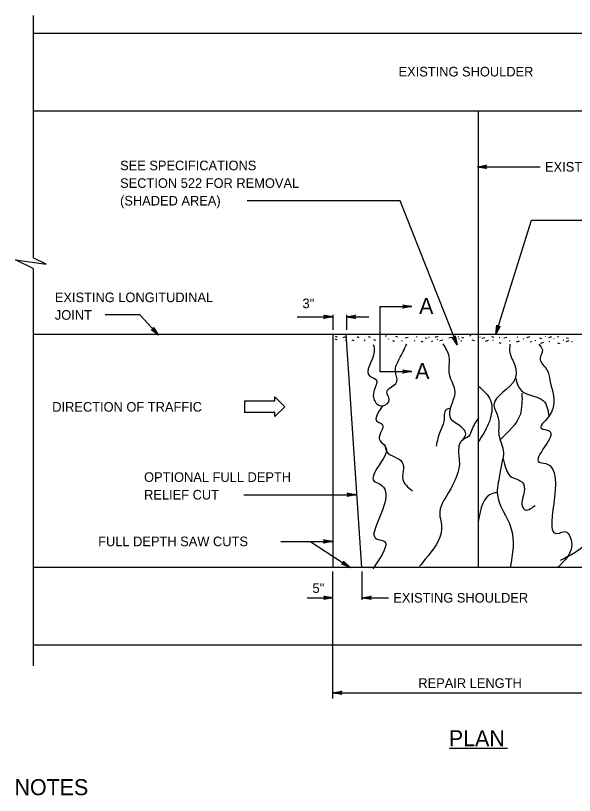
# Model space of a CAD drawing. Extents: x 1.45 to 8.06, y 0.17 to 9.98.
# Drawn here: x 1.461 to 4.954, y 5.108 to 9.976 of the extents above; entities that cross this region are included whole.
import ezdxf

# ---------------------------------------------------------------- set-up
doc = ezdxf.new("R2010")
doc.units = 0
for name, color, linetype in [('DETL-DIMS', 7, 'Continuous'), ('DETL-LINE', 7, 'Continuous'), ('DETL-NOTE', 7, 'Continuous'), ('DETL-PATT', 7, 'Continuous'), ('DETL-TITL', 7, 'Continuous')]:
    doc.layers.add(name, color=color, linetype=linetype)

msp = doc.modelspace()

# ---------------------------------------------------------------- linework, layer by layer
at = {"layer": 'DETL-DIMS'}
for p, q in [((4.3469, 9.0319), (4.7396, 9.0319)), ((4.3469, 9.0319), (4.7396, 9.0319)), ((3.8636, 8.8204), (2.9091, 8.8204)), ((3.8636, 8.8204), (2.9091, 8.8204)), ((4.2201, 7.9197), (3.8636, 8.8204)), ((4.2201, 7.9197), (3.8636, 8.8204)), ((4.462, 7.987), (4.6853, 8.6995)), ((4.6853, 8.6995), (5.057, 8.6995)), ((4.6853, 8.6995), (4.8907, 8.6995)), ((3.7368, 8.1593), (3.938, 8.1593)), ((3.7368, 8.1593), (3.7368, 7.7526)), ((3.7368, 8.1593), (3.938, 8.1593)), ((3.7368, 8.1593), (3.7368, 7.7526)), ((2.2385, 8.1071), (2.021, 8.1071)), ((2.2385, 8.1071), (2.021, 8.1071)), ((2.3533, 7.9802), (2.2385, 8.1071)), ((2.3533, 7.9802), (2.2385, 8.1071)), ((3.2205, 8.0952), (3.4438, 8.0952)), ((3.2205, 8.0952), (3.4438, 8.0952)), ((3.4438, 8.1081), (3.4438, 8.015)), ((3.4438, 8.1081), (3.4438, 8.015)), ((3.53, 8.1081), (3.53, 8.015)), ((3.53, 8.1081), (3.53, 8.015)), ((3.53, 8.0952), (3.6695, 8.0952)), ((3.53, 8.0952), (3.6695, 8.0952)), ((3.7368, 7.7537), (3.938, 7.7537)), ((3.7368, 7.7537), (3.938, 7.7537)), ((2.8924, 7.5708), (2.8924, 7.4958)), ((2.8924, 7.5708), (2.8924, 7.4958)), ((2.8884, 6.9849), (3.5893, 6.9849)), ((2.8884, 6.9849), (3.5893, 6.9849)), ((3.1188, 6.6935), (3.4429, 6.6935)), ((3.1188, 6.6935), (3.4429, 6.6935)), ((3.3063, 6.6902), (3.5531, 6.5305)), ((3.3063, 6.6902), (3.5531, 6.5305)), ((3.4438, 5.7125), (3.4438, 6.5066)), ((3.4438, 5.7158), (3.4438, 6.5066)), ((3.6264, 6.3295), (3.6264, 6.5066)), ((3.6264, 6.3295), (3.6264, 6.5066)), ((3.2823, 6.3416), (3.4438, 6.3416)), ((3.2823, 6.3416), (3.4438, 6.3416)), ((3.6264, 6.3416), (3.7916, 6.3416)), ((3.6264, 6.3416), (3.7916, 6.3416)), ((3.4438, 5.7487), (5.2619, 5.7487)), ((3.4438, 5.7487), (5.2619, 5.7487))]:
    msp.add_line(p, q, dxfattribs=at)
for points in [[(4.3469, 9.0319), (4.4034, 9.0425), (4.3991, 9.0395), (4.3968, 9.0357), (4.3962, 9.0319), (4.3968, 9.0281), (4.3991, 9.0244), (4.4034, 9.0213), (4.3469, 9.0319), (4.3991, 9.0244), (4.3968, 9.0281), (4.3469, 9.0319), (4.3962, 9.0319), (4.3968, 9.0357), (4.3469, 9.0319), (4.3991, 9.0395)], [(4.3469, 9.0319), (4.4034, 9.0425), (4.3991, 9.0395), (4.3968, 9.0357), (4.3962, 9.0319), (4.3968, 9.0281), (4.3991, 9.0244), (4.4034, 9.0213), (4.3469, 9.0319), (4.3991, 9.0244), (4.3968, 9.0281), (4.3469, 9.0319), (4.3962, 9.0319), (4.3968, 9.0357), (4.3469, 9.0319), (4.3991, 9.0395)], [(3.938, 8.1593), (3.8816, 8.1487), (3.8859, 8.1518), (3.8882, 8.1555), (3.8888, 8.1593), (3.8882, 8.1631), (3.8859, 8.1669), (3.8816, 8.1699), (3.938, 8.1593), (3.8859, 8.1669), (3.8882, 8.1631), (3.938, 8.1593), (3.8888, 8.1593), (3.8882, 8.1555), (3.938, 8.1593), (3.8859, 8.1518)], [(3.938, 8.1593), (3.8816, 8.1487), (3.8859, 8.1518), (3.8882, 8.1555), (3.8888, 8.1593), (3.8882, 8.1631), (3.8859, 8.1669), (3.8816, 8.1699), (3.938, 8.1593), (3.8859, 8.1669), (3.8882, 8.1631), (3.938, 8.1593), (3.8888, 8.1593), (3.8882, 8.1555), (3.938, 8.1593), (3.8859, 8.1518)], [(3.938, 8.1593), (3.8816, 8.1487), (3.8859, 8.1518), (3.8882, 8.1555), (3.8888, 8.1593), (3.8882, 8.1631), (3.8859, 8.1669), (3.8816, 8.1699), (3.938, 8.1593), (3.8859, 8.1669), (3.8882, 8.1631), (3.938, 8.1593), (3.8888, 8.1593), (3.8882, 8.1555), (3.938, 8.1593), (3.8859, 8.1518)], [(3.938, 8.1593), (3.8816, 8.1487), (3.8859, 8.1518), (3.8882, 8.1555), (3.8888, 8.1593), (3.8882, 8.1631), (3.8859, 8.1669), (3.8816, 8.1699), (3.938, 8.1593), (3.8859, 8.1669), (3.8882, 8.1631), (3.938, 8.1593), (3.8888, 8.1593), (3.8882, 8.1555), (3.938, 8.1593), (3.8859, 8.1518)], [(3.4438, 8.0952), (3.3873, 8.0846), (3.3916, 8.0877), (3.3939, 8.0915), (3.3945, 8.0952), (3.3939, 8.099), (3.3916, 8.1028), (3.3873, 8.1058), (3.4438, 8.0952), (3.3916, 8.1028), (3.3939, 8.099), (3.4438, 8.0952), (3.3945, 8.0952), (3.3939, 8.0915), (3.4438, 8.0952), (3.3916, 8.0877)], [(3.4438, 8.0952), (3.3873, 8.0846), (3.3916, 8.0877), (3.3939, 8.0915), (3.3945, 8.0952), (3.3939, 8.099), (3.3916, 8.1028), (3.3873, 8.1058), (3.4438, 8.0952), (3.3916, 8.1028), (3.3939, 8.099), (3.4438, 8.0952), (3.3945, 8.0952), (3.3939, 8.0915), (3.4438, 8.0952), (3.3916, 8.0877)], [(3.53, 8.0952), (3.5864, 8.1058), (3.5821, 8.1028), (3.5798, 8.099), (3.5792, 8.0952), (3.5798, 8.0915), (3.5821, 8.0877), (3.5864, 8.0846), (3.53, 8.0952), (3.5821, 8.0877), (3.5798, 8.0915), (3.53, 8.0952), (3.5792, 8.0952), (3.5798, 8.099), (3.53, 8.0952), (3.5821, 8.1028)], [(3.53, 8.0952), (3.5864, 8.1058), (3.5821, 8.1028), (3.5798, 8.099), (3.5792, 8.0952), (3.5798, 8.0915), (3.5821, 8.0877), (3.5864, 8.0846), (3.53, 8.0952), (3.5821, 8.0877), (3.5798, 8.0915), (3.53, 8.0952), (3.5792, 8.0952), (3.5798, 8.099), (3.53, 8.0952), (3.5821, 8.1028)], [(4.462, 7.987), (4.4688, 8.0441), (4.4704, 8.0391), (4.4733, 8.0358), (4.4767, 8.034), (4.4805, 8.0335), (4.4848, 8.0345), (4.489, 8.0378), (4.462, 7.987), (4.4848, 8.0345), (4.4805, 8.0335), (4.462, 7.987), (4.4767, 8.034), (4.4733, 8.0358), (4.462, 7.987), (4.4704, 8.0391)], [(2.3533, 7.9802), (2.3076, 8.015), (2.3127, 8.0137), (2.317, 8.0146), (2.3203, 8.0167), (2.3227, 8.0197), (2.324, 8.0239), (2.3233, 8.0292), (2.3533, 7.9802), (2.324, 8.0239), (2.3227, 8.0197), (2.3533, 7.9802), (2.3203, 8.0167), (2.317, 8.0146), (2.3533, 7.9802), (2.3127, 8.0137)], [(2.3533, 7.9802), (2.3076, 8.015), (2.3127, 8.0137), (2.317, 8.0146), (2.3203, 8.0167), (2.3227, 8.0197), (2.324, 8.0239), (2.3233, 8.0292), (2.3533, 7.9802), (2.324, 8.0239), (2.3227, 8.0197), (2.3533, 7.9802), (2.3203, 8.0167), (2.317, 8.0146), (2.3533, 7.9802), (2.3127, 8.0137)], [(4.2201, 7.9197), (4.1894, 7.9683), (4.1939, 7.9654), (4.1982, 7.9647), (4.202, 7.9655), (4.2052, 7.9675), (4.2079, 7.971), (4.2091, 7.9761), (4.2201, 7.9197), (4.2079, 7.971), (4.2052, 7.9675), (4.2201, 7.9197), (4.202, 7.9655), (4.1982, 7.9647), (4.2201, 7.9197), (4.1939, 7.9654)], [(4.2201, 7.9197), (4.1894, 7.9683), (4.1939, 7.9654), (4.1982, 7.9647), (4.202, 7.9655), (4.2052, 7.9675), (4.2079, 7.971), (4.2091, 7.9761), (4.2201, 7.9197), (4.2079, 7.971), (4.2052, 7.9675), (4.2201, 7.9197), (4.202, 7.9655), (4.1982, 7.9647), (4.2201, 7.9197), (4.1939, 7.9654)], [(4.2201, 7.9197), (4.1894, 7.9683), (4.1939, 7.9654), (4.1982, 7.9647), (4.202, 7.9655), (4.2052, 7.9675), (4.2079, 7.971), (4.2091, 7.9761), (4.2201, 7.9197), (4.2079, 7.971), (4.2052, 7.9675), (4.2201, 7.9197), (4.202, 7.9655), (4.1982, 7.9647), (4.2201, 7.9197), (4.1939, 7.9654)], [(4.2201, 7.9197), (4.1894, 7.9683), (4.1939, 7.9654), (4.1982, 7.9647), (4.202, 7.9655), (4.2052, 7.9675), (4.2079, 7.971), (4.2091, 7.9761), (4.2201, 7.9197), (4.2079, 7.971), (4.2052, 7.9675), (4.2201, 7.9197), (4.202, 7.9655), (4.1982, 7.9647), (4.2201, 7.9197), (4.1939, 7.9654)], [(3.938, 7.7537), (3.8816, 7.7431), (3.8859, 7.7462), (3.8882, 7.75), (3.8888, 7.7537), (3.8882, 7.7575), (3.8859, 7.7613), (3.8816, 7.7643), (3.938, 7.7537), (3.8859, 7.7613), (3.8882, 7.7575), (3.938, 7.7537), (3.8888, 7.7537), (3.8882, 7.75), (3.938, 7.7537), (3.8859, 7.7462)], [(3.938, 7.7537), (3.8816, 7.7431), (3.8859, 7.7462), (3.8882, 7.75), (3.8888, 7.7537), (3.8882, 7.7575), (3.8859, 7.7613), (3.8816, 7.7643), (3.938, 7.7537), (3.8859, 7.7613), (3.8882, 7.7575), (3.938, 7.7537), (3.8888, 7.7537), (3.8882, 7.75), (3.938, 7.7537), (3.8859, 7.7462)], [(3.938, 7.7537), (3.8816, 7.7431), (3.8859, 7.7462), (3.8882, 7.75), (3.8888, 7.7537), (3.8882, 7.7575), (3.8859, 7.7613), (3.8816, 7.7643), (3.938, 7.7537), (3.8859, 7.7613), (3.8882, 7.7575), (3.938, 7.7537), (3.8888, 7.7537), (3.8882, 7.75), (3.938, 7.7537), (3.8859, 7.7462)], [(3.938, 7.7537), (3.8816, 7.7431), (3.8859, 7.7462), (3.8882, 7.75), (3.8888, 7.7537), (3.8882, 7.7575), (3.8859, 7.7613), (3.8816, 7.7643), (3.938, 7.7537), (3.8859, 7.7613), (3.8882, 7.7575), (3.938, 7.7537), (3.8888, 7.7537), (3.8882, 7.75), (3.938, 7.7537), (3.8859, 7.7462)], [(2.8924, 7.5711), (3.0816, 7.5711), (3.0816, 7.596), (3.1431, 7.5345)], [(2.8924, 7.5711), (3.0816, 7.5711), (3.0816, 7.596), (3.1431, 7.5345)], [(3.1431, 7.5345), (3.0816, 7.473), (3.0816, 7.498), (2.8928, 7.498)], [(3.1431, 7.5345), (3.0816, 7.473), (3.0816, 7.498), (2.8928, 7.498)], [(3.5893, 6.9849), (3.5328, 6.9743), (3.5372, 6.9773), (3.5394, 6.9811), (3.5401, 6.9849), (3.5394, 6.9887), (3.5372, 6.9925), (3.5328, 6.9955), (3.5893, 6.9849), (3.5372, 6.9925), (3.5394, 6.9887), (3.5893, 6.9849), (3.5401, 6.9849), (3.5394, 6.9811), (3.5893, 6.9849), (3.5372, 6.9773)], [(3.5893, 6.9849), (3.5328, 6.9743), (3.5372, 6.9773), (3.5394, 6.9811), (3.5401, 6.9849), (3.5394, 6.9887), (3.5372, 6.9925), (3.5328, 6.9955), (3.5893, 6.9849), (3.5372, 6.9925), (3.5394, 6.9887), (3.5893, 6.9849), (3.5401, 6.9849), (3.5394, 6.9811), (3.5893, 6.9849), (3.5372, 6.9773)], [(3.4429, 6.6935), (3.3864, 6.6829), (3.3908, 6.6859), (3.393, 6.6897), (3.3937, 6.6935), (3.393, 6.6973), (3.3908, 6.7011), (3.3864, 6.7041), (3.4429, 6.6935), (3.3908, 6.7011), (3.393, 6.6973), (3.4429, 6.6935), (3.3937, 6.6935), (3.393, 6.6897), (3.4429, 6.6935), (3.3908, 6.6859)], [(3.4429, 6.6935), (3.3864, 6.6829), (3.3908, 6.6859), (3.393, 6.6897), (3.3937, 6.6935), (3.393, 6.6973), (3.3908, 6.7011), (3.3864, 6.7041), (3.4429, 6.6935), (3.3908, 6.7011), (3.393, 6.6973), (3.4429, 6.6935), (3.3937, 6.6935), (3.393, 6.6897), (3.4429, 6.6935), (3.3908, 6.6859)], [(3.5531, 6.5305), (3.4999, 6.5523), (3.5052, 6.5525), (3.5092, 6.5545), (3.5118, 6.5573), (3.5133, 6.5608), (3.5134, 6.5652), (3.5114, 6.5701), (3.5531, 6.5305), (3.5134, 6.5652), (3.5133, 6.5608), (3.5531, 6.5305), (3.5118, 6.5573), (3.5092, 6.5545), (3.5531, 6.5305), (3.5052, 6.5525)], [(3.5531, 6.5305), (3.4999, 6.5523), (3.5052, 6.5525), (3.5092, 6.5545), (3.5118, 6.5573), (3.5133, 6.5608), (3.5134, 6.5652), (3.5114, 6.5701), (3.5531, 6.5305), (3.5134, 6.5652), (3.5133, 6.5608), (3.5531, 6.5305), (3.5118, 6.5573), (3.5092, 6.5545), (3.5531, 6.5305), (3.5052, 6.5525)], [(3.4438, 6.3416), (3.3873, 6.331), (3.3916, 6.334), (3.3939, 6.3378), (3.3945, 6.3416), (3.3939, 6.3454), (3.3916, 6.3492), (3.3873, 6.3522), (3.4438, 6.3416), (3.3916, 6.3492), (3.3939, 6.3454), (3.4438, 6.3416), (3.3945, 6.3416), (3.3939, 6.3378), (3.4438, 6.3416), (3.3916, 6.334)], [(3.4438, 6.3416), (3.3873, 6.331), (3.3916, 6.334), (3.3939, 6.3378), (3.3945, 6.3416), (3.3939, 6.3454), (3.3916, 6.3492), (3.3873, 6.3522), (3.4438, 6.3416), (3.3916, 6.3492), (3.3939, 6.3454), (3.4438, 6.3416), (3.3945, 6.3416), (3.3939, 6.3378), (3.4438, 6.3416), (3.3916, 6.334)], [(3.6264, 6.3416), (3.6829, 6.3522), (3.6786, 6.3492), (3.6763, 6.3454), (3.6757, 6.3416), (3.6763, 6.3378), (3.6786, 6.334), (3.6829, 6.331), (3.6264, 6.3416), (3.6786, 6.334), (3.6763, 6.3378), (3.6264, 6.3416), (3.6757, 6.3416), (3.6763, 6.3454), (3.6264, 6.3416), (3.6786, 6.3492)], [(3.6264, 6.3416), (3.6829, 6.3522), (3.6786, 6.3492), (3.6763, 6.3454), (3.6757, 6.3416), (3.6763, 6.3378), (3.6786, 6.334), (3.6829, 6.331), (3.6264, 6.3416), (3.6786, 6.334), (3.6763, 6.3378), (3.6264, 6.3416), (3.6757, 6.3416), (3.6763, 6.3454), (3.6264, 6.3416), (3.6786, 6.3492)], [(3.4438, 5.7487), (3.5002, 5.7593), (3.4959, 5.7563), (3.4937, 5.7525), (3.493, 5.7487), (3.4937, 5.7449), (3.4959, 5.7411), (3.5002, 5.7381), (3.4438, 5.7487), (3.4959, 5.7411), (3.4937, 5.7449), (3.4438, 5.7487), (3.493, 5.7487), (3.4937, 5.7525), (3.4438, 5.7487), (3.4959, 5.7563)], [(3.4438, 5.7487), (3.5002, 5.7593), (3.4959, 5.7563), (3.4937, 5.7525), (3.493, 5.7487), (3.4937, 5.7449), (3.4959, 5.7411), (3.5002, 5.7381), (3.4438, 5.7487), (3.4959, 5.7411), (3.4937, 5.7449), (3.4438, 5.7487), (3.493, 5.7487), (3.4937, 5.7525), (3.4438, 5.7487), (3.4959, 5.7563)], [(3.4438, 5.7487), (3.5002, 5.7593), (3.4959, 5.7563), (3.4937, 5.7525), (3.493, 5.7487), (3.4937, 5.7449), (3.4959, 5.7411), (3.5002, 5.7381), (3.4438, 5.7487), (3.4959, 5.7411), (3.4937, 5.7449), (3.4438, 5.7487), (3.493, 5.7487), (3.4937, 5.7525), (3.4438, 5.7487), (3.4959, 5.7563)], [(3.4438, 5.7487), (3.5002, 5.7593), (3.4959, 5.7563), (3.4937, 5.7525), (3.493, 5.7487), (3.4937, 5.7449), (3.4959, 5.7411), (3.5002, 5.7381), (3.4438, 5.7487), (3.4959, 5.7411), (3.4937, 5.7449), (3.4438, 5.7487), (3.493, 5.7487), (3.4937, 5.7525), (3.4438, 5.7487), (3.4959, 5.7563)]]:
    msp.add_lwpolyline(points, dxfattribs=at)
at = {"layer": 'DETL-LINE'}
for p, q in [((1.5705, 9.9759), (1.5705, 8.4639)), ((1.5705, 9.8658), (7.1352, 9.8658)), ((1.5705, 9.381), (7.1352, 9.381)), ((4.3529, 9.381), (4.3529, 6.5325)), ((1.5705, 8.3971), (1.5705, 5.9166)), ((1.5705, 7.987), (7.1352, 7.987)), ((3.4438, 7.987), (3.4438, 6.5325)), ((3.5248, 7.987), (3.6222, 6.5288)), ((1.5705, 6.5325), (3.4438, 6.5325)), ((3.4438, 6.5325), (5.2619, 6.5325)), ((1.5705, 6.0476), (7.1352, 6.0476))]:
    msp.add_line(p, q, dxfattribs=at)
msp.add_lwpolyline([(1.5705, 8.3971), (1.461, 8.4507), (1.6532, 8.4246), (1.5705, 8.4639)], dxfattribs=at)
for points in [[(3.6966, 7.9222), (3.7025, 7.878), (3.676, 7.7248), (3.7172, 7.6982), (3.7143, 7.6717), (3.6995, 7.5833), (3.7526, 7.5391), (3.7967, 7.5804), (3.781, 7.6262), (3.7967, 7.6481), (3.8439, 7.6924), (3.835, 7.7572), (3.8586, 7.8309), (3.9057, 7.9252)], [(3.6966, 7.9222), (3.7025, 7.878), (3.676, 7.7248), (3.7172, 7.6982), (3.7143, 7.6717), (3.6995, 7.5833), (3.7526, 7.5391), (3.7967, 7.5804), (3.781, 7.6262), (3.7967, 7.6481), (3.8439, 7.6924), (3.835, 7.7572), (3.8586, 7.8309), (3.9057, 7.9252)], [(4.2555, 7.3262), (4.2744, 7.364), (4.2178, 7.4278), (4.1847, 7.4537), (4.1847, 7.5435), (4.2083, 7.6262), (4.1729, 7.7348), (4.1705, 7.8482), (4.1328, 7.9262)], [(4.55, 7.9238), (4.55, 7.8742), (4.5807, 7.7939), (4.5831, 7.7089), (4.4509, 7.5435), (4.4769, 7.4656), (4.4816, 7.3569), (4.5099, 7.2482), (4.5028, 7.1963), (4.4863, 7.1065), (4.4721, 6.986), (4.5571, 6.7782), (4.5524, 6.5301)], [(4.7318, 7.9238), (4.7531, 7.8884), (4.7389, 7.8364), (4.7814, 7.7655), (4.8003, 7.6994), (4.7908, 7.4703), (4.746, 7.3994), (4.7956, 7.3829), (4.7318, 7.1892), (4.7743, 7.1797), (4.8593, 6.7451), (4.8924, 6.7545), (4.9348, 6.6931), (4.8475, 6.5301)], [(5.0671, 7.9238), (5.0387, 7.6711), (5.1332, 7.5128), (5.119, 7.3569), (5.0387, 7.1608), (5.0387, 7.1301), (5.0883, 6.9624), (5.0954, 6.8679), (5.0246, 6.679), (4.864, 6.575)], [(4.5854, 7.7136), (4.6232, 7.6333), (4.7601, 7.5718), (4.7932, 7.4726)], [(4.3541, 7.6616), (4.4296, 7.5742), (4.4273, 7.4585), (4.4155, 7.4254), (4.3541, 7.3167)], [(4.6256, 7.6191), (4.6138, 7.4844), (4.4887, 7.3285)], [(3.7548, 7.5396), (3.7243, 7.4396), (3.7527, 7.4254), (3.7338, 7.3333), (3.7692, 7.2908), (3.7196, 7.149), (3.7007, 7.0711), (3.7361, 7.0522), (3.7078, 6.7711), (3.7031, 6.7238), (3.7385, 6.7026), (3.7527, 6.7002), (3.6937, 6.5231)], [(4.18, 7.5246), (4.1517, 7.5152), (4.1375, 7.4419), (4.1139, 7.3805), (4.0903, 7.2884)], [(4.357, 7.4679), (4.3122, 7.39), (4.2933, 7.3498), (4.2532, 7.3262), (4.2296, 7.2435), (4.2343, 7.201), (4.1658, 6.9978), (4.1115, 6.8608), (4.121, 6.8089), (4.1233, 6.7711), (4.0218, 6.5821), (3.9864, 6.5396)], [(3.7692, 7.2955), (3.781, 7.253), (3.8778, 7.1868), (3.8849, 7.149), (3.8802, 7.0829), (3.9415, 7.0097)], [(4.5075, 7.2081), (4.5264, 7.1443), (4.5524, 7.1018), (4.6303, 7.0593), (4.6397, 7.0049), (4.6279, 6.9152), (4.6397, 6.8939), (4.7082, 6.9175)], [(4.4723, 6.9973), (4.4438, 6.9931), (4.3517, 6.8183)]]:
    msp.add_spline(points, degree=3, dxfattribs=at)
at = {"layer": 'DETL-PATT'}
for p, q in [((3.4566, 7.9579), (3.4696, 7.9541)), ((3.4584, 7.9747), (3.4715, 7.9709)), ((3.5256, 7.9709), (3.5069, 7.9653)), ((3.5237, 7.9485), (3.5293, 7.9523)), ((3.5629, 7.9523), (3.576, 7.9485)), ((3.5965, 7.9728), (3.6058, 7.9672)), ((3.6394, 7.9485), (3.645, 7.9523)), ((3.6637, 7.9728), (3.6767, 7.9691)), ((3.6973, 7.9541), (3.7103, 7.9504)), ((3.7738, 7.9747), (3.7794, 7.9784)), ((3.7887, 7.9579), (3.7924, 7.956)), ((3.8167, 7.9467), (3.8297, 7.9429)), ((3.8353, 7.9747), (3.8484, 7.9709)), ((3.8726, 7.9467), (3.8764, 7.9448)), ((3.9137, 7.9672), (3.895, 7.9616)), ((3.951, 7.9429), (3.9566, 7.9467)), ((3.9659, 7.9691), (3.9715, 7.9728)), ((3.9939, 7.9429), (4.007, 7.9392)), ((4.02, 7.9653), (4.0331, 7.9616)), ((4.0424, 7.9709), (4.0462, 7.9691)), ((4.0611, 7.9411), (4.0667, 7.9448)), ((4.1003, 7.9728), (4.0816, 7.9672)), ((4.0947, 7.956), (4.0984, 7.9541)), ((4.132, 7.9504), (4.1133, 7.9448)), ((4.188, 7.9672), (4.1693, 7.9616)), ((4.2253, 7.9728), (4.229, 7.9709)), ((4.229, 7.9597), (4.2327, 7.9579)), ((4.2439, 7.9448), (4.2495, 7.9485)), ((4.2477, 7.9691), (4.2607, 7.9653)), ((4.2999, 7.9765), (4.3055, 7.9803)), ((4.313, 7.9523), (4.326, 7.9485)), ((4.3615, 7.9709), (4.3652, 7.9691)), ((4.3932, 7.9653), (4.3745, 7.9597)), ((4.4137, 7.9467), (4.3951, 7.9411)), ((4.4361, 7.9728), (4.4492, 7.9691)), ((4.4417, 7.9523), (4.4454, 7.9504)), ((4.4809, 7.9355), (4.494, 7.9317)), ((4.4828, 7.9653), (4.4884, 7.9691)), ((4.5313, 7.9672), (4.5126, 7.9616)), ((4.5462, 7.9467), (4.5499, 7.9448)), ((4.6078, 7.9429), (4.5891, 7.9373)), ((4.5947, 7.9672), (4.6003, 7.9709)), ((4.6339, 7.9597), (4.6376, 7.9579)), ((4.6731, 7.9709), (4.6544, 7.9653)), ((4.6787, 7.9392), (4.6843, 7.9429)), ((4.7067, 7.9504), (4.7104, 7.9485)), ((4.7347, 7.9635), (4.7477, 7.9597)), ((4.7608, 7.9355), (4.7421, 7.9299)), ((4.7701, 7.9728), (4.7738, 7.9709)), ((4.8093, 7.9709), (4.7906, 7.9653)), ((4.7944, 7.9429), (4.7981, 7.9411)), ((4.8242, 7.9597), (4.8279, 7.9579)), ((4.8485, 7.9709), (4.8541, 7.9747)), ((4.8821, 7.9523), (4.8858, 7.9504)), ((4.9194, 7.9448), (4.9007, 7.9392)), ((4.9044, 7.9653), (4.9175, 7.9616)), ((4.9362, 7.9429), (4.9399, 7.9411)), ((4.8485, 7.9336), (4.8615, 7.9299))]:
    msp.add_line(p, q, dxfattribs=at)
at = {"layer": 'DETL-TITL'}
for p, q in [((4.1733, 5.4023), (4.5104, 5.4023)), ((4.2029, 5.4023), (4.5358, 5.4023))]:
    msp.add_line(p, q, dxfattribs=at)

# ---------------------------------------------------------------- texts
at = {"layer": 'DETL-NOTE'}
for s, height, p in [('EXISTING SHOULDER', 0.06, (3.8545, 9.596)), ('EXISTING SHOULDER', 0.06, (3.8545, 9.596)), ('SEE SPECIFICATIONS', 0.06, (2.1142, 9.0104)), ('EXISTING TRANSVERSE JOINT', 0.06, (4.7699, 9.0019)), ('SECTION 522 FOR REMOVAL', 0.06, (2.1142, 8.9004)), ('(SHADED AREA)', 0.06, (2.1142, 8.7904)), ('EXISTING LONGITUDINAL', 0.06, (1.7062, 8.1871)), ('3"', 0.06038, (3.2539, 8.149)), ('3"', 0.06, (3.2542, 8.1492)), ('A', 0.1, (3.983, 8.1132)), ('JOINT', 0.06, (1.7062, 8.0771)), ('A', 0.1, (3.9584, 7.707)), ('DIRECTION OF TRAFFIC', 0.06, (1.6902, 7.5033)), ('OPTIONAL FULL DEPTH', 0.06, (2.2642, 7.0649)), ('RELIEF CUT', 0.06, (2.2642, 6.9549)), ('FULL DEPTH SAW CUTS', 0.06, (1.977, 6.6635)), ('5"', 0.06, (3.3167, 6.3719)), ('EXISTING SHOULDER', 0.06, (3.8219, 6.3116)), ('REPAIR LENGTH', 0.06, (3.9781, 5.779)), ('NOTES', 0.1, (1.4545, 5.1093))]:
    msp.add_text(s, height=height, dxfattribs=at).set_placement(p)
at = {"layer": 'DETL-TITL'}
msp.add_text('PLAN', height=0.1, dxfattribs=at).set_placement((4.1689, 5.4148))

doc.saveas('drawing.dxf')
